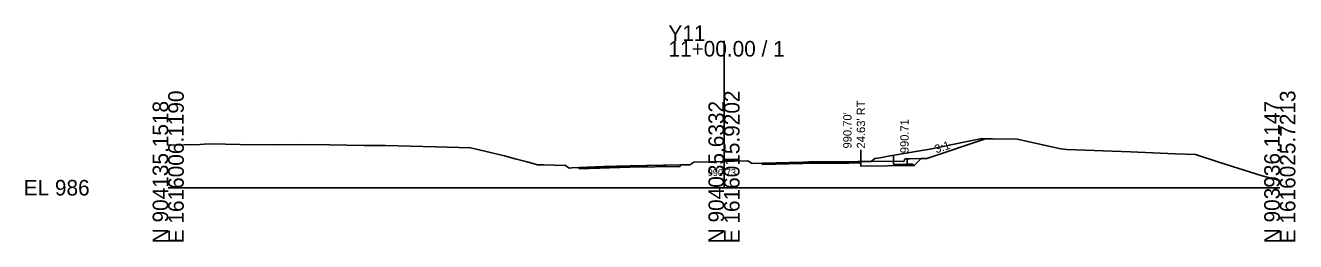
# Model space of a CAD drawing. Extents: x -26 to 203, y -10 to 2019.
# Drawn here: x -25.7 to 202.8, y 990.3 to 1029.2 of the extents above; entities that cross this region are included whole.
import ezdxf

# ---------------------------------------------------------------- set-up
doc = ezdxf.new("R2010")
doc.units = 0
for name, color, linetype in [('Exist Cross Section Cell', 7, 'Continuous'), ('Exist XS Center Line Elevation Label', 7, 'Continuous'), ('Exist XS Ground Line', 7, 'Continuous'), ('Prop XS Dump Level', 7, 'Continuous'), ('Prop XS Earthwork Shape', 7, 'Continuous'), ('Prop XS EOT Tick Mark', 7, 'Continuous'), ('Prop XS Finish Grade', 7, 'Continuous'), ('Prop XS Finish Grade CurbGutter', 7, 'Continuous'), ('Prop XS Finish Grade Earthwork', 7, 'Continuous'), ('Prop XS Finish Grade Pavement', 7, 'Continuous'), ('Prop XS Hydro Elevations', 7, 'Continuous'), ('Prop XS Pvmt Edge Slope', 7, 'Continuous'), ('Prop XS Side Slope Text', 7, 'Continuous'), ('Prop XS Subgrade CurbGutter', 7, 'Continuous'), ('Prop XS Subgrade Earthwork', 7, 'Continuous')]:
    doc.layers.add(name, color=color, linetype=linetype)

msp = doc.modelspace()

# ---------------------------------------------------------------- linework, layer by layer
at = {"layer": 'Exist Cross Section Cell'}
for p, q in [((100, 1000), (100, 1026.39)), ((0, 1000), (100, 1000)), ((100, 1000), (200, 1000))]:
    msp.add_line(p, q, dxfattribs=at)
at = {"layer": 'Exist XS Ground Line'}
for p, q in [((6.49, 1007.83), (7.65, 1007.86)), ((7.65, 1007.86), (12.96, 1007.76)), ((137.04, 1006.91), (143.44, 1008.22)), ((143.44, 1008.22), (146.15, 1008.79)), ((146.15, 1008.79), (148.28, 1008.8)), ((148.28, 1008.8), (152.77, 1008.74)), ((152.77, 1008.74), (160.58, 1007.01)), ((0, 1007.63), (5.76, 1007.76)), ((5.76, 1007.76), (6.49, 1007.83)), ((12.96, 1007.76), (18.98, 1007.72)), ((18.98, 1007.72), (24.11, 1007.74)), ((24.11, 1007.74), (29.03, 1007.72)), ((29.03, 1007.72), (35.26, 1007.61)), ((35.26, 1007.61), (39.08, 1007.61)), ((39.08, 1007.61), (48.1, 1007.33)), ((48.1, 1007.33), (54.37, 1007.16)), ((54.37, 1007.16), (55.94, 1006.81)), ((55.94, 1006.81), (60.51, 1005.71)), ((60.51, 1005.71), (62.45, 1005.21)), ((128.08, 1005.4), (129.53, 1005.65)), ((129.53, 1005.65), (137.04, 1006.91)), ((160.58, 1007.01), (161.09, 1006.91)), ((161.09, 1006.91), (161.71, 1006.88)), ((161.71, 1006.88), (173.14, 1006.45)), ((173.14, 1006.45), (181.15, 1006.1)), ((181.15, 1006.1), (184.84, 1005.97)), ((184.84, 1005.97), (189.21, 1004.55)), ((62.45, 1005.21), (64.61, 1004.64)), ((64.61, 1004.64), (66.46, 1004.14)), ((66.46, 1004.14), (67.55, 1004.11)), ((67.55, 1004.11), (71.5, 1004.01)), ((71.5, 1004.01), (72.16, 1003.53)), ((72.16, 1003.53), (72.64, 1003.56)), ((72.64, 1003.56), (73.95, 1003.63)), ((73.95, 1003.63), (78.37, 1003.79)), ((78.37, 1003.79), (83.04, 1003.95)), ((83.04, 1003.95), (89.62, 1004.05)), ((89.62, 1004.05), (92.13, 1004.09)), ((92.13, 1004.09), (92.55, 1004.1)), ((92.55, 1004.1), (93.87, 1004.12)), ((93.87, 1004.12), (94.57, 1004.62)), ((94.57, 1004.62), (100, 1004.73)), ((100, 1004.73), (101.87, 1004.76)), ((101.87, 1004.76), (104.31, 1004.82)), ((104.31, 1004.82), (105.09, 1004.36)), ((105.09, 1004.36), (106.84, 1004.44)), ((106.84, 1004.44), (114.16, 1004.62)), ((114.16, 1004.62), (115.27, 1004.64)), ((115.27, 1004.64), (124.11, 1004.71)), ((124.11, 1004.71), (124.63, 1004.71)), ((124.63, 1004.71), (126.46, 1004.7)), ((126.46, 1004.7), (127.13, 1005.23)), ((127.13, 1005.23), (128.08, 1005.4)), ((189.21, 1004.55), (196.8, 1002.13)), ((196.8, 1002.13), (200, 1001.3))]:
    msp.add_line(p, q, dxfattribs=at)
at = {"layer": 'Prop XS Dump Level'}
msp.add_line((130.47, 1004.76), (114.47, 1004.6), dxfattribs=at)
at = {"layer": 'Prop XS Earthwork Shape'}
for points in [[(132.5, 1005.08), (132.59, 1005.17), (132.72, 1005.2), (132.97, 1005.2), (133.5, 1005.21), (135.5, 1005.26), (136.47, 1005.28), (147.02, 1008.79), (146.15, 1008.79), (143.44, 1008.22), (137.04, 1006.91), (129.53, 1005.65), (128.08, 1005.4), (127.13, 1005.23), (126.46, 1004.7), (124.63, 1004.71), (124.63, 1003.87), (134.22, 1003.97), (133.97, 1004.22), (132.97, 1004.21), (130.47, 1004.18), (130.47, 1004.76), (132.22, 1004.71), (132.34, 1004.73), (132.43, 1004.83)], [(132.5, 1005.08), (132.59, 1005.17), (132.72, 1005.2), (132.97, 1005.2), (132.97, 1004.21), (130.47, 1004.18), (130.47, 1004.76), (132.22, 1004.71), (132.34, 1004.73), (132.43, 1004.83)], [(133.5, 1005.21), (135.5, 1005.26), (134.22, 1003.97), (133.97, 1004.22), (132.97, 1004.21), (132.97, 1005.2)]]:
    msp.add_lwpolyline(points, close=True, dxfattribs=at)
at = {"layer": 'Prop XS EOT Tick Mark'}
msp.add_line((130.47, 1004.76), (130.47, 1005.76), dxfattribs=at)
at = {"layer": 'Prop XS Finish Grade'}
msp.add_line((132.97, 1005.2), (135.5, 1005.26), dxfattribs=at)
at = {"layer": 'Prop XS Finish Grade CurbGutter'}
for p, q in [((130.47, 1004.76), (132.22, 1004.71)), ((132.22, 1004.71), (132.34, 1004.73)), ((132.34, 1004.73), (132.43, 1004.83)), ((132.43, 1004.83), (132.5, 1005.08)), ((132.5, 1005.08), (132.59, 1005.17)), ((132.72, 1005.2), (132.59, 1005.17)), ((132.97, 1005.2), (132.72, 1005.2))]:
    msp.add_line(p, q, dxfattribs=at)
at = {"layer": 'Prop XS Finish Grade Earthwork'}
for p, q in [((136.47, 1005.28), (147.02, 1008.79)), ((133.5, 1005.21), (136.47, 1005.28))]:
    msp.add_line(p, q, dxfattribs=at)
at = {"layer": 'Prop XS Finish Grade Pavement'}
for p, q in [((83.04, 1003.95), (73.95, 1003.63)), ((73.95, 1003.63), (73.96, 1003.38)), ((83.05, 1003.7), (73.96, 1003.38)), ((92.13, 1004.09), (83.04, 1003.95)), ((92.14, 1003.84), (83.04, 1003.7)), ((92.13, 1004.09), (92.14, 1003.84)), ((114.16, 1004.62), (106.84, 1004.44)), ((106.84, 1004.44), (106.84, 1004.19)), ((114.17, 1004.37), (106.84, 1004.19)), ((122.47, 1004.68), (114.16, 1004.62)), ((122.47, 1004.43), (114.16, 1004.37)), ((130.47, 1004.75), (122.47, 1004.68)), ((124.63, 1004.45), (122.47, 1004.43))]:
    msp.add_line(p, q, dxfattribs=at)
at = {"layer": 'Prop XS Hydro Elevations'}
msp.add_line((124.63, 1004.7), (124.63, 1006.82), dxfattribs=at)
at = {"layer": 'Prop XS Pvmt Edge Slope'}
for p, q in [((132.97, 1004.21), (133.97, 1004.22)), ((133.97, 1004.22), (134.22, 1003.97))]:
    msp.add_line(p, q, dxfattribs=at)
at = {"layer": 'Prop XS Subgrade CurbGutter'}
for p, q in [((130.47, 1004.76), (130.47, 1004.18)), ((130.47, 1004.18), (132.97, 1004.21)), ((132.97, 1004.21), (132.97, 1005.2))]:
    msp.add_line(p, q, dxfattribs=at)
at = {"layer": 'Prop XS Subgrade Earthwork'}
for p, q in [((124.63, 1004.71), (124.63, 1003.87)), ((124.63, 1003.87), (134.22, 1003.97)), ((134.22, 1003.97), (135.5, 1005.26))]:
    msp.add_line(p, q, dxfattribs=at)

# ---------------------------------------------------------------- texts
at = {"layer": 'Exist Cross Section Cell'}
for s, p in [('Y11', (90, 1026.39)), ('11+00.00 / 1', (90, 1023.59)), ('EL 986', (-26, 998.6))]:
    msp.add_text(s, height=2.8, dxfattribs=at).set_placement(p)
for s, p in [('E 1616006.1190', (2.8, 990)), ('E 1616015.9202', (102.8, 990)), ('E 1616025.7213', (202.8, 990)), ('N 904135.1518', (0, 990)), ('N 904035.6332', (100, 990)), ('N 903936.1147', (200, 990))]:
    msp.add_text(s, height=2.8, rotation=90, dxfattribs=at).set_placement(p)
at = {"layer": 'Exist XS Center Line Elevation Label'}
msp.add_text('990.73', height=1.25, dxfattribs=at).set_placement((97.05, 1002.1))
at = {"layer": 'Prop XS Hydro Elevations'}
for s, p in [("24.63' RT", (125.38, 1007.05)), ("990.70'", (122.95, 1007.05)), ('990.71', (133.22, 1006.2))]:
    msp.add_text(s, height=1.5, rotation=90, dxfattribs=at).set_placement(p)
at = {"layer": 'Prop XS Side Slope Text'}
msp.add_text('3:1', height=1.5, rotation=18.4349, dxfattribs=at).set_placement((138.18, 1006.16))

doc.saveas('drawing.dxf')
